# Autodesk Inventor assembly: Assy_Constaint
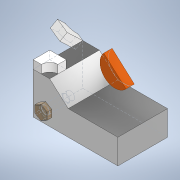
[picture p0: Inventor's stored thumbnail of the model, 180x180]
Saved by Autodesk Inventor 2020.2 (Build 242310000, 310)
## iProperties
Created: 2020-01
Part Number: Assy_Constaint
Document SubType Name: Assembly
Designer: thira
Author: thira
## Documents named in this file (5)
- C:\Users\thira\OneDrive\เดสก์ท็อป\INV-01 Intro to Modeling_2020\Assy_Constraint\Assy_Constaint.iam
- C:\Users\thira\OneDrive\เดสก์ท็อป\INV-01 Intro to Modeling_2020\Assy_Constraint\Main Part.ipt
- C:\Users\thira\OneDrive\เดสก์ท็อป\INV-01 Intro to Modeling_2020\Assy_Constraint\Tangent.ipt
- C:\Users\thira\OneDrive\เดสก์ท็อป\INV-01 Intro to Modeling_2020\Assy_Constraint\Part1.ipt
- C:\Users\thira\OneDrive\เดสก์ท็อป\INV-01 Intro to Modeling_2020\Assy_Constraint\Part2.ipt
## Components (5 placed, 4 different names)
1. Main Part:1 — Tangent:1, Tangent:2, Mate:1, Mate:2, Mate:3, Angle:1, Insert:1
2. Tangent:1 — Tangent:1, Tangent:2, Angle:1
3. Part1:1 — Mate:1, Mate:2
4. Part1:2 — Mate:3
5. Part2:1 — Insert:1
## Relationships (7: Mate 3, Tangent 2, Angle 1, Insert 1)
- Tangent:1: Main Part:1 ↔ Tangent:1
- Tangent:2: Main Part:1 ↔ Tangent:1
- Mate:1: Main Part:1 ↔ Part1:1
- Mate:2: Main Part:1 ↔ Part1:1
- Mate:3: Main Part:1 ↔ Part1:2
- Angle:1: Main Part:1 ↔ Tangent:1
- Insert:1: Main Part:1 ↔ Part2:1
